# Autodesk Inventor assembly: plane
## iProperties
Author: Administrator
Created: 2001-01
Part Number: plane
Document SubType Name: Assembly
Designer: Administrator
Control State: 0
Master: False
Checked Out: False
PropertySet Name: Design Tracking Control
Shininess: 0.0
PropertySet Name: _Private Model Information
Density: 0.0
Volumn: 0.0
Area: 0.0
PropertySet Name: Model Information
